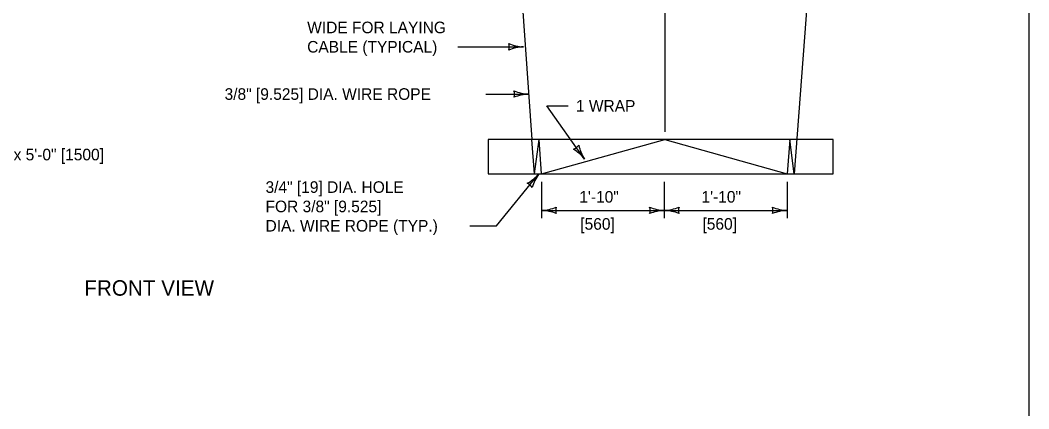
# Model space of a CAD drawing. Extents: x 49991.4 to 50021, y 49987.6 to 50011.4.
# Drawn here: x 50011.53 to 50016.75, y 49993.69 to 49995.7 of the extents above; entities that cross this region are included whole.
import ezdxf

# ---------------------------------------------------------------- set-up
doc = ezdxf.new("R2010")
doc.units = 0
for name, color, linetype in [('Level 1', 7, 'Continuous'), ('Level 2', 7, 'Continuous'), ('Level 3', 7, 'Continuous'), ('Level 4', 7, 'Continuous')]:
    doc.layers.add(name, color=color, linetype=linetype)

msp = doc.modelspace()

# ---------------------------------------------------------------- linework, layer by layer
at = {"layer": 'Level 1'}
for p, q in [((50014.1023, 49996.1487), (50014.1791, 49995.0841)), ((50015.6308, 49996.1483), (50015.5362, 49994.9056)), ((50013.9522, 49995.0841), (50013.9522, 49994.9056)), ((50015.7372, 49995.0841), (50013.9522, 49995.0841)), ((50014.192, 49994.9056), (50014.2161, 49995.0841)), ((50014.229, 49994.9056), (50014.8666, 49995.0841)), ((50015.5128, 49995.0841), (50015.4992, 49994.9056)), ((50015.7372, 49994.9056), (50015.7372, 49995.0841)), ((50013.9522, 49994.9056), (50015.7372, 49994.9056))]:
    msp.add_line(p, q, dxfattribs=at)
msp.add_lwpolyline([(49999.3835, 49998.9992), (50016.7501, 49998.9992), (50016.7501, 49987.7988), (49999.3835, 49987.7988)], close=True, dxfattribs=at)
at = {"layer": 'Level 3'}
for p, q in [((50014.8666, 49996.5315), (50014.8666, 49995.1241)), ((50013.7965, 49995.5629), (50014.135, 49995.5629)), ((50013.9414, 49995.3186), (50014.1622, 49995.3186)), ((50014.4514, 49994.982), (50014.2555, 49995.2576)), ((50014.2555, 49995.2576), (50014.3669, 49995.2576)), ((50013.9962, 49994.6377), (50014.2153, 49994.9056)), ((50014.229, 49994.8656), (50014.229, 49994.6773)), ((50014.8641, 49994.8656), (50014.8641, 49994.6774)), ((50015.4992, 49994.8656), (50015.4992, 49994.6774)), ((50014.229, 49994.7173), (50014.8641, 49994.7174)), ((50014.8641, 49994.7174), (50015.4992, 49994.7174)), ((50013.858, 49994.6377), (50013.9962, 49994.6377))]:
    msp.add_line(p, q, dxfattribs=at)
for centre, radius, start, end in [((50014.1442, 49995.785), 0.2223, 247.456, 267.6395), ((50014.0068, 49995.5629), 0.0548, 342.1388, 17.8612), ((50014.1465, 49995.3302), 0.233, 92.8273, 112.0772), ((50014.1713, 49995.5407), 0.2223, 247.456, 267.6395), ((50014.034, 49995.3186), 0.0548, 342.1388, 17.8612), ((50014.1737, 49995.0859), 0.233, 92.8273, 112.0772), ((50014.3771, 49995.0865), 0.0548, 287.5445, 323.2669), ((50014.2684, 49994.8378), 0.233, 38.233, 57.4829), ((50014.6378, 49995.1032), 0.2223, 192.8617, 213.0452), ((50014.0491, 49995.0533), 0.2223, 298.1784, 318.3619), ((50014.4027, 49994.7672), 0.233, 143.5497, 162.7995), ((50014.1341, 49994.8064), 0.0548, 32.8612, 68.5835), ((50014.2175, 49994.95), 0.233, 272.8318, 292.0817), ((50014.2199, 49994.4952), 0.2223, 67.4605, 87.644), ((50014.3572, 49994.7173), 0.0548, 162.1433, 197.8657), ((50014.8732, 49994.9395), 0.2223, 247.465, 267.6485), ((50014.7359, 49994.7174), 0.0548, 342.1478, 17.8702), ((50014.8756, 49994.4847), 0.233, 92.8363, 112.0862), ((50014.8526, 49994.9501), 0.233, 272.8273, 292.0772), ((50014.8549, 49994.4953), 0.2223, 67.456, 87.6395), ((50014.9923, 49994.7174), 0.0548, 162.1388, 197.8612), ((50015.5083, 49994.9395), 0.2223, 247.4605, 267.644), ((50015.371, 49994.7174), 0.0548, 342.1433, 17.8657), ((50015.5107, 49994.4847), 0.233, 92.8318, 112.0817)]:
    msp.add_arc(centre, radius, start, end, dxfattribs=at)
at = {"layer": 'Level 4'}
for p, q in [((50014.192, 49994.9056), (50014.1791, 49995.0841)), ((50014.229, 49994.9056), (50014.2161, 49995.0841)), ((50014.8666, 49995.0841), (50015.4992, 49994.9056)), ((50015.5362, 49994.9056), (50015.5128, 49995.0841))]:
    msp.add_line(p, q, dxfattribs=at)

# ---------------------------------------------------------------- texts
at = {"layer": 'Level 2'}
for s, height, p in [('WIDE FOR LAYING', 0.06, (50013.0162, 49995.6329)), ('CABLE (TYPICAL)', 0.06, (50013.0162, 49995.5329)), ('3/8" [9.525] DIA. WIRE ROPE', 0.06, (50012.5889, 49995.2886)), ('1 WRAP', 0.06, (50014.4069, 49995.2276)), ('6" [150] DIA. x 5\'-0" [1500]', 0.06, (50011.0227, 49994.9759)), ('3/4" [19] DIA. HOLE', 0.06, (50012.8007, 49994.8077)), ('1\'-10"', 0.06, (50014.4242, 49994.7573)), ('1\'-10"', 0.06, (50015.0563, 49994.7574)), ('FOR 3/8" [9.525]', 0.06, (50012.8007, 49994.7077)), ('DIA. WIRE ROPE (TYP.)', 0.06, (50012.8007, 49994.6077)), ('[560]', 0.06, (50014.4294, 49994.6174)), ('[560]', 0.06, (50015.0615, 49994.6174)), ('FRONT VIEW', 0.08, (50011.8628, 49994.2764))]:
    msp.add_text(s, height=height, dxfattribs=at).set_placement(p)

doc.saveas('drawing.dxf')
